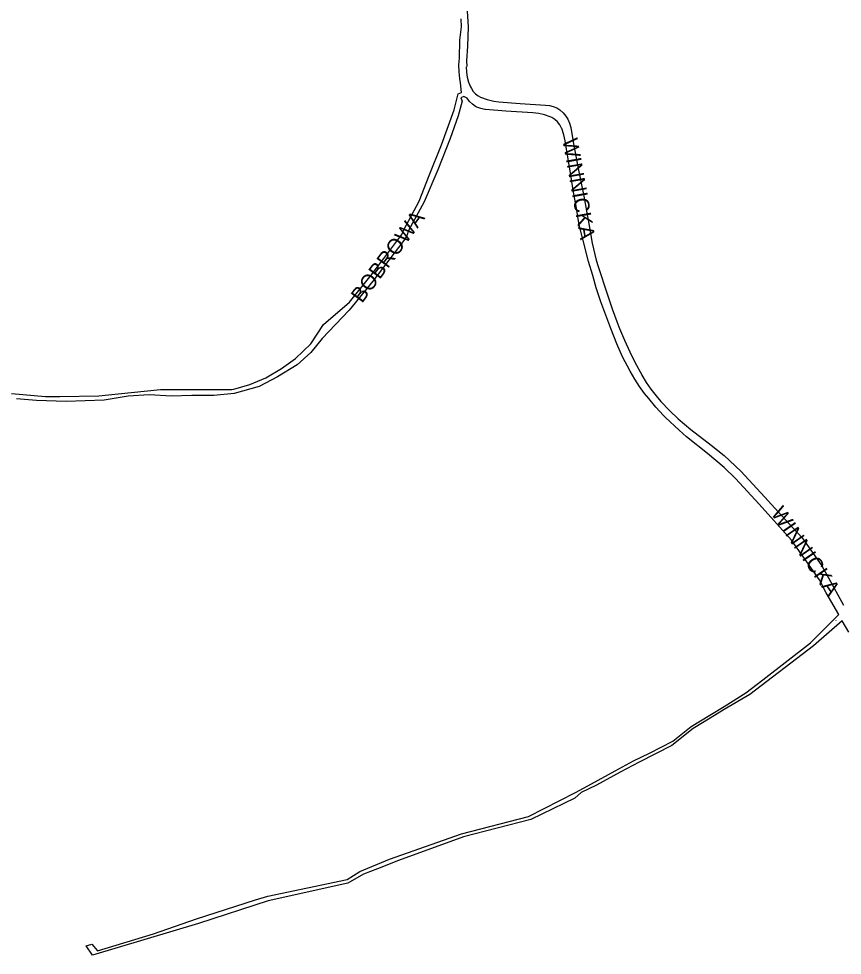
# Model space of a CAD drawing. Extents: x -304109 to -273954, y 21500 to 39796.
# Drawn here: x -299661 to -299123, y 27894 to 28505 of the extents above; entities that cross this region are included whole.
import ezdxf

# ---------------------------------------------------------------- set-up
doc = ezdxf.new("R2010")
doc.units = 0
doc.layers.add('krawedzie_ulic', color=7, linetype='Continuous')
doc.layers.add('nazwy_ulic', color=7, linetype='Continuous')

msp = doc.modelspace()

# ---------------------------------------------------------------- linework, layer by layer
at = {"layer": 'krawedzie_ulic'}
for points in [[(-299367.941, 28474.084), (-299367.98, 28477.746), (-299367.442, 28487.203), (-299367.064, 28500), (-299367.555, 28510.136)], [(-299665.345, 28260.456), (-299643.139, 28258.614), (-299633.837, 28258.638), (-299608.269, 28259.025), (-299587.322, 28261.051), (-299568.103, 28263.083), (-299547.873, 28263.128), (-299521.442, 28263.206), (-299520.12, 28263.355), (-299509.792, 28266.378), (-299499.207, 28270.722), (-299489.072, 28276.898), (-299479.852, 28283.432), (-299469.911, 28292.864), (-299461.535, 28305.554), (-299444.665, 28320.205), (-299430.48, 28337.812), (-299422.314, 28348.621), (-299410.523, 28364.405), (-299409.192, 28367.351), (-299399.222, 28386.089), (-299392.664, 28402.751), (-299384.57, 28422.918), (-299376.366, 28445.679), (-299373.792, 28456.148), (-299371.501, 28457.159), (-299372.244, 28463.467), (-299372.711, 28466.182), (-299373.142, 28470.592), (-299373.173, 28475.022), (-299372.804, 28479.437), (-299372.564, 28491.134), (-299371.54, 28500), (-299371.81, 28505.23)], [(-299368.399, 28473.78), (-299368.295, 28470.431), (-299367.792, 28467.118), (-299366.899, 28463.889), (-299365.628, 28460.788), (-299365.038, 28459.633), (-299363.888, 28457.755), (-299362.418, 28456.116), (-299360.677, 28454.769), (-299359.211, 28453.971), (-299354.829, 28452.534), (-299350.34, 28451.482), (-299347.225, 28450.988), (-299333.2, 28449.881), (-299316.684, 28448.716), (-299314.156, 28448.548), (-299311.687, 28447.984), (-299309.336, 28447.04), (-299307.239, 28445.791), (-299305.194, 28443.872), (-299303.443, 28441.683), (-299302.176, 28439.572), (-299300.954, 28436.929), (-299300.105, 28434.143), (-299299.66, 28431.428), (-299298.113, 28422.371), (-299295.615, 28408.532), (-299291.761, 28389.45), (-299288.463, 28371.234), (-299286.164, 28358.768), (-299283.658, 28347.573), (-299282.349, 28343.5), (-299276.458, 28325.583), (-299273.185, 28315.86), (-299270.009, 28307.511), (-299268.75, 28303.947), (-299268.384, 28302.998), (-299265.14, 28295.219), (-299261.532, 28287.602), (-299258.299, 28281.027), (-299253.752, 28272.578), (-299253.693, 28272.467), (-299250.958, 28267.781), (-299247.886, 28263.309), (-299244.493, 28259.075), (-299241.29, 28255.349), (-299235.815, 28249.474), (-299230.054, 28243.88), (-299221.892, 28237.042), (-299208.455, 28226.681), (-299200, 28220.032), (-299189.171, 28209.818), (-299173.535, 28192.896), (-299160.132, 28178.26), (-299149.065, 28166.267), (-299136.327, 28147.973), (-299131.812, 28140.096), (-299122.193, 28122.273)], [(-299310.538, 28439.47), (-299312.541, 28440.822), (-299313.545, 28441.226), (-299317.25, 28442.441), (-299321.06, 28443.27), (-299324.934, 28443.704), (-299342.517, 28444.923), (-299355.779, 28445.977), (-299356.293, 28446.031), (-299359.008, 28446.557), (-299361.62, 28447.468), (-299362.364, 28447.895), (-299364.45, 28449.401), (-299366.277, 28451.211), (-299367.803, 28453.283), (-299370.036, 28454.459), (-299372.021, 28453.499), (-299371.112, 28451.462), (-299373.735, 28441.806), (-299378.966, 28427.073), (-299386.908, 28406.549), (-299395.818, 28385.571), (-299406.144, 28366.884), (-299407.324, 28363.379), (-299409.265, 28360.333), (-299418.963, 28347.493), (-299429.324, 28333.74), (-299444.835, 28314.865), (-299462.428, 28296.403), (-299469.827, 28287.168), (-299478.747, 28279.31), (-299491.682, 28271.362), (-299503.697, 28264.987), (-299519.875, 28260.456), (-299533.349, 28259.12), (-299547.58, 28259.109), (-299560.899, 28258.689), (-299575.534, 28259.696), (-299589.108, 28258.666), (-299604.822, 28256.116), (-299629.731, 28255.169), (-299649.044, 28255.833), (-299662.001, 28256.988)], [(-299303.739, 28425.397), (-299304.732, 28429.495), (-299306.109, 28433.48), (-299306.214, 28433.736), (-299307.331, 28435.878), (-299308.786, 28437.807), (-299310.538, 28439.47)], [(-299118.687, 28104.725), (-299122.948, 28112.043), (-299141.722, 28095.677), (-299183.182, 28063.96), (-299200, 28054.15), (-299209.116, 28048.432), (-299220.319, 28041.7), (-299234.179, 28030.703), (-299255.561, 28019.777), (-299267.831, 28013.251), (-299283.31, 28004.649), (-299293.393, 28000), (-299297.511, 27996.186), (-299326.322, 27982.237), (-299370.145, 27970.884), (-299412.702, 27955.445), (-299426.398, 27950.14), (-299435.495, 27946.653), (-299445.743, 27940.741), (-299497.854, 27929.196), (-299543.301, 27914.305), (-299612.567, 27893.636), (-299616.499, 27899.742), (-299612.926, 27900.863), (-299609.275, 27896.44), (-299572.622, 27907.687), (-299544.528, 27917.475), (-299505.929, 27929.764), (-299498.067, 27932.199), (-299446.167, 27943.137), (-299438.013, 27948.315), (-299418.535, 27956.39), (-299395.088, 27964.664), (-299371.591, 27972.887), (-299327.718, 27984.189), (-299297.157, 28000), (-299286.61, 28005.625), (-299271.132, 28014.023), (-299259.319, 28020.652), (-299248.731, 28025.708), (-299233.509, 28033.498), (-299221.535, 28043.127), (-299209.466, 28050.366), (-299200, 28056.031), (-299185.874, 28064.926), (-299174.734, 28073.414), (-299143.651, 28097.659), (-299125.256, 28116.083), (-299133.399, 28130.338), (-299137.862, 28138.723), (-299146.084, 28150.462), (-299156.132, 28164.691), (-299177.2, 28188.321), (-299192.684, 28205.091), (-299200, 28212.155), (-299210.912, 28221.348), (-299224.703, 28232.269), (-299229.473, 28236.469), (-299238.438, 28244.768), (-299239.672, 28246.038), (-299244.601, 28251.467), (-299249.226, 28257.156), (-299252.027, 28260.52), (-299255.397, 28265.121), (-299258.436, 28269.946), (-299261.345, 28275.052), (-299266.32, 28284.412), (-299270.074, 28292.874), (-299274.09, 28302.843), (-299280.491, 28320.254), (-299281.012, 28321.697), (-299283.584, 28329.52), (-299285.774, 28337.458), (-299288.591, 28346.722), (-299292.106, 28360.412), (-299294.615, 28370.641), (-299296.411, 28381.529), (-299298.661, 28393.334), (-299300.303, 28404.578), (-299303.148, 28421.317), (-299303.739, 28425.397)], [(-299127.019, 28112.414), (-299127.167, 28112.246)]]:
    msp.add_lwpolyline(points, dxfattribs=at)

# ---------------------------------------------------------------- texts
at = {"layer": 'nazwy_ulic'}
for s, rotation, p in [('WINNICKA', 280.152781, (-299305.697, 28426.203)), ('BOBROWA', 53.54545, (-299436.482, 28318.983)), ('WINNICKA', 304.628664, (-299169.875, 28182.292))]:
    msp.add_text(s, height=10, rotation=rotation, dxfattribs=at).set_placement(p)

doc.saveas('drawing.dxf')
